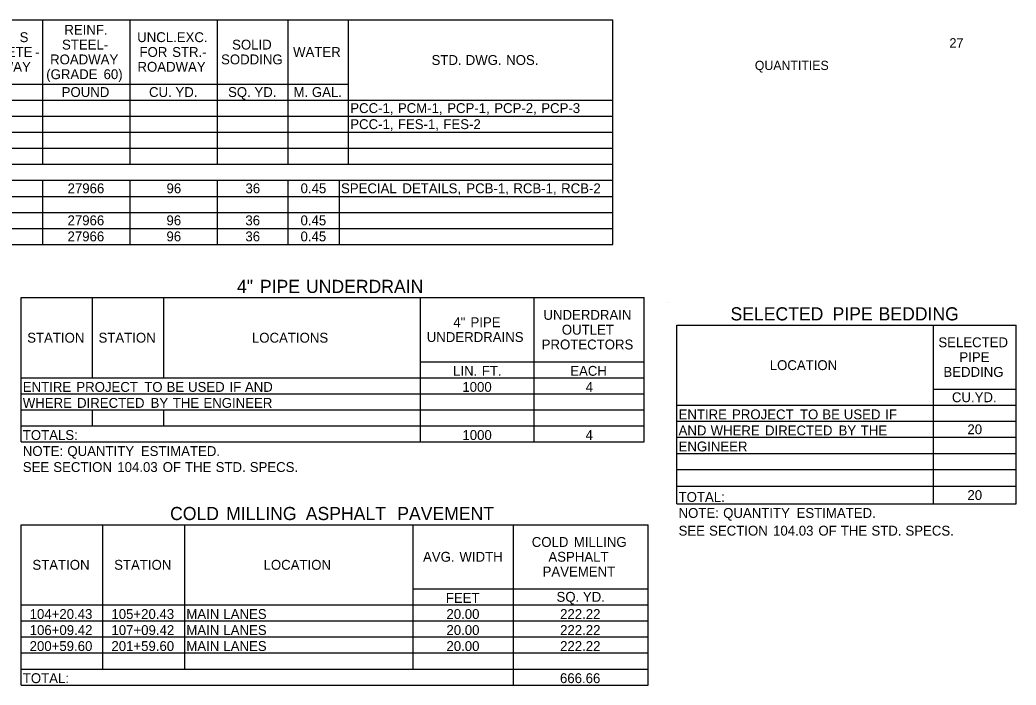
# Model space of a CAD drawing. Extents: x 1334738 to 1334853, y 402732 to 402753.
# Drawn here: x 1334837.83 to 1334852.97, y 402742.15 to 402752.26 of the extents above; entities that cross this region are included whole.
import ezdxf

# ---------------------------------------------------------------- set-up
doc = ezdxf.new("R2010")
doc.units = 0
doc.layers.add('Default', color=7, linetype='Continuous')
doc.layers.add('R_No Plot', color=7, linetype='Continuous')

msp = doc.modelspace()

# ---------------------------------------------------------------- linework, layer by layer
at = {"layer": 'Default'}
for p, q in [((1334821.842, 402752.258), (1334846.839, 402752.258)), ((1334838.174, 402751.04), (1334838.174, 402752.258)), ((1334839.502, 402751.04), (1334839.502, 402752.258)), ((1334840.831, 402751.04), (1334840.831, 402752.258)), ((1334841.903, 402751.283), (1334841.903, 402752.258)), ((1334841.903, 402751.04), (1334841.903, 402752.258)), ((1334842.823, 402750.065), (1334842.823, 402752.258)), ((1334846.839, 402748.846), (1334846.839, 402752.258)), ((1334832.787, 402751.283), (1334842.823, 402751.283)), ((1334821.842, 402751.04), (1334846.839, 402751.04)), ((1334838.174, 402750.065), (1334838.174, 402751.04)), ((1334838.174, 402750.065), (1334838.174, 402751.04)), ((1334839.502, 402750.065), (1334839.502, 402751.04)), ((1334839.502, 402750.065), (1334839.502, 402751.04)), ((1334840.831, 402750.065), (1334840.831, 402751.04)), ((1334840.831, 402750.065), (1334840.831, 402751.04)), ((1334841.903, 402750.065), (1334841.903, 402751.04)), ((1334841.903, 402750.065), (1334841.903, 402751.04)), ((1334842.683, 402751.04), (1334846.839, 402751.04)), ((1334821.842, 402750.796), (1334846.839, 402750.796)), ((1334846.839, 402748.846), (1334846.839, 402750.796)), ((1334821.842, 402750.552), (1334846.839, 402750.552)), ((1334842.683, 402750.552), (1334846.839, 402750.552)), ((1334821.842, 402750.308), (1334846.839, 402750.308)), ((1334841.903, 402750.308), (1334846.839, 402750.308)), ((1334821.842, 402750.065), (1334846.839, 402750.065)), ((1334821.842, 402749.821), (1334846.839, 402749.821)), ((1334838.174, 402748.846), (1334838.174, 402749.821)), ((1334838.174, 402748.846), (1334838.174, 402749.821)), ((1334839.502, 402748.846), (1334839.502, 402749.821)), ((1334839.502, 402748.846), (1334839.502, 402749.821)), ((1334840.831, 402748.846), (1334840.831, 402749.821)), ((1334840.831, 402748.846), (1334840.831, 402749.821)), ((1334841.903, 402748.846), (1334841.903, 402749.821)), ((1334841.903, 402748.846), (1334841.903, 402749.821)), ((1334842.683, 402749.333), (1334842.683, 402749.821)), ((1334842.683, 402748.846), (1334842.683, 402749.821)), ((1334821.842, 402749.577), (1334846.839, 402749.577)), ((1334821.842, 402749.333), (1334846.839, 402749.333)), ((1334825.864, 402749.333), (1334841.903, 402749.333)), ((1334841.903, 402749.333), (1334842.683, 402749.333)), ((1334842.683, 402749.333), (1334846.839, 402749.333)), ((1334821.842, 402749.09), (1334846.839, 402749.09)), ((1334842.683, 402748.846), (1334842.683, 402749.09)), ((1334821.842, 402748.846), (1334846.839, 402748.846)), ((1334837.846, 402748.038), (1334847.315, 402748.038)), ((1334837.846, 402745.844), (1334837.846, 402748.038)), ((1334837.846, 402745.844), (1334837.846, 402748.038)), ((1334838.93, 402746.819), (1334838.93, 402748.038)), ((1334840.015, 402746.819), (1334840.015, 402748.038)), ((1334843.915, 402745.844), (1334843.915, 402748.038)), ((1334845.646, 402745.844), (1334845.646, 402748.038)), ((1334847.315, 402745.844), (1334847.315, 402748.038)), ((1334847.315, 402745.844), (1334847.315, 402748.038)), ((1334847.668, 402747.961), (1334847.668, 402747.961)), ((1334847.814, 402747.62), (1334852.969, 402747.62)), ((1334847.814, 402744.902), (1334847.814, 402747.62)), ((1334847.814, 402744.902), (1334847.814, 402747.62)), ((1334851.714, 402744.902), (1334851.714, 402747.62)), ((1334852.969, 402744.902), (1334852.969, 402747.62)), ((1334852.969, 402744.902), (1334852.969, 402747.62)), ((1334843.915, 402747.063), (1334847.315, 402747.063)), ((1334837.846, 402746.819), (1334847.315, 402746.819)), ((1334837.846, 402746.819), (1334847.315, 402746.819)), ((1334837.846, 402746.575), (1334847.315, 402746.575)), ((1334851.714, 402746.645), (1334852.969, 402746.645)), ((1334847.814, 402746.401), (1334852.969, 402746.401)), ((1334851.714, 402744.902), (1334851.714, 402746.401)), ((1334837.846, 402746.332), (1334847.315, 402746.332)), ((1334838.93, 402746.088), (1334838.93, 402746.332)), ((1334838.93, 402746.088), (1334838.93, 402746.332)), ((1334840.015, 402746.088), (1334840.015, 402746.332)), ((1334840.015, 402746.088), (1334840.015, 402746.332)), ((1334843.915, 402745.844), (1334843.915, 402746.332)), ((1334837.846, 402746.088), (1334847.315, 402746.088)), ((1334847.814, 402746.158), (1334852.969, 402746.158)), ((1334837.846, 402745.844), (1334847.315, 402745.844)), ((1334847.814, 402745.914), (1334852.969, 402745.914)), ((1334847.814, 402745.67), (1334852.969, 402745.67)), ((1334847.814, 402745.426), (1334852.969, 402745.426)), ((1334847.814, 402745.17), (1334852.969, 402745.17)), ((1334847.814, 402744.902), (1334852.969, 402744.902)), ((1334837.846, 402744.586), (1334847.376, 402744.586)), ((1334837.846, 402742.148), (1334837.846, 402744.586)), ((1334837.846, 402742.148), (1334837.846, 402744.586)), ((1334839.089, 402742.392), (1334839.089, 402744.586)), ((1334840.332, 402742.392), (1334840.332, 402744.586)), ((1334843.805, 402742.392), (1334843.805, 402744.586)), ((1334845.329, 402742.148), (1334845.329, 402744.586)), ((1334847.376, 402742.148), (1334847.376, 402744.586)), ((1334847.376, 402742.148), (1334847.376, 402744.586)), ((1334843.805, 402743.611), (1334847.376, 402743.611)), ((1334843.805, 402742.392), (1334843.805, 402743.611)), ((1334837.846, 402743.367), (1334847.376, 402743.367)), ((1334839.089, 402742.392), (1334839.089, 402743.367)), ((1334840.332, 402742.392), (1334840.332, 402743.367)), ((1334845.329, 402742.392), (1334845.329, 402743.367)), ((1334837.846, 402743.123), (1334847.376, 402743.123)), ((1334837.846, 402742.879), (1334847.376, 402742.879)), ((1334837.846, 402742.636), (1334847.376, 402742.636)), ((1334837.846, 402742.392), (1334839.089, 402742.392)), ((1334837.846, 402742.392), (1334847.376, 402742.392)), ((1334839.089, 402742.392), (1334840.332, 402742.392)), ((1334840.332, 402742.392), (1334843.805, 402742.392)), ((1334845.329, 402742.392), (1334847.376, 402742.392)), ((1334837.846, 402742.148), (1334847.376, 402742.148))]:
    msp.add_line(p, q, dxfattribs=at)

# ---------------------------------------------------------------- texts
for s, height, p in [('REINF.', 0.15, (1334838.502, 402752.033)), (' S', 0.15, (1334837.766, 402751.921)), ('UNCL.EXC.', 0.15, (1334839.609, 402751.921)), ('CONCRETE', 0.15, (1334836.892, 402751.696)), ('STEEL-', 0.15, (1334838.466, 402751.808)), ('FOR', 0.15, (1334839.644, 402751.696)), (' STR.-', 0.15, (1334840.085, 402751.696)), ('SOLID', 0.15, (1334841.052, 402751.808)), ('WATER', 0.15, (1334841.979, 402751.696)), ('-', 0.15, (1334838.058, 402751.696)), ('ROADWAY', 0.15, (1334838.285, 402751.583)), ('SODDING', 0.15, (1334840.884, 402751.583)), ('STD.', 0.15, (1334844.084, 402751.574)), (' DWG.', 0.15, (1334844.547, 402751.574)), (' NOS.', 0.15, (1334845.162, 402751.574)), ('ROADWAY', 0.15, (1334836.956, 402751.471)), ('ROADWAY', 0.15, (1334839.613, 402751.471)), ('(GRADE', 0.15, (1334838.226, 402751.358)), (' 60)', 0.15, (1334839.042, 402751.358)), ('POUND', 0.15, (1334838.461, 402751.087)), ('CU. YD.', 0.15, (1334839.789, 402751.087)), ('SQ. YD.', 0.15, (1334840.99, 402751.087)), ('M. GAL.', 0.15, (1334841.986, 402751.087)), ('PCC-1,', 0.15, (1334842.848, 402750.843)), (' PCM-1,', 0.15, (1334843.516, 402750.843)), (' PCP-1,', 0.15, (1334844.266, 402750.843)), (' PCP-2,', 0.15, (1334844.981, 402750.843)), (' PCP-3', 0.15, (1334845.696, 402750.843)), ('PCC-1,', 0.15, (1334842.848, 402750.599)), (' FES-1,', 0.15, (1334843.516, 402750.599)), (' FES-2', 0.15, (1334844.208, 402750.599)), ('27966', 0.15, (1334838.551, 402749.624)), ('96', 0.15, (1334840.055, 402749.624)), ('36', 0.15, (1334841.255, 402749.624)), ('0.45', 0.15, (1334842.093, 402749.624)), ('SPECIAL', 0.15, (1334842.707, 402749.624)), (' DETAILS,', 0.15, (1334843.585, 402749.624)), (' PCB-1,', 0.15, (1334844.557, 402749.624)), (' RCB-1,', 0.15, (1334845.272, 402749.624)), (' RCB-2', 0.15, (1334845.998, 402749.624)), ('27966', 0.15, (1334838.55, 402749.137)), ('96', 0.15, (1334840.054, 402749.137)), ('36', 0.15, (1334841.254, 402749.137)), ('0.45', 0.15, (1334842.092, 402749.137)), ('27966', 0.15, (1334838.55, 402748.893)), ('96', 0.15, (1334840.054, 402748.893)), ('36', 0.15, (1334841.254, 402748.893)), ('0.45', 0.15, (1334842.092, 402748.893)), ('4"', 0.2, (1334841.126, 402748.108)), (' PIPE', 0.2, (1334841.4, 402748.108)), (' UNDERDRAIN', 0.2, (1334842.101, 402748.108)), ('SELECTED', 0.2, (1334848.628, 402747.691)), (' PIPE', 0.2, (1334850.105, 402747.691)), (' BEDDING', 0.2, (1334850.806, 402747.691)), ('4"', 0.15, (1334844.415, 402747.588)), (' PIPE', 0.15, (1334844.62, 402747.588)), ('UNDERDRAIN', 0.15, (1334845.785, 402747.7)), ('OUTLET', 0.15, (1334846.064, 402747.475)), ('STATION', 0.15, (1334837.937, 402747.353)), ('STATION', 0.15, (1334839.021, 402747.353)), ('LOCATIONS', 0.15, (1334841.353, 402747.353)), ('UNDERDRAINS', 0.15, (1334844.011, 402747.363)), ('SELECTED', 0.15, (1334851.788, 402747.283)), ('PROTECTORS', 0.15, (1334845.758, 402747.25)), ('PIPE', 0.15, (1334852.108, 402747.058)), ('LIN.', 0.15, (1334844.411, 402746.849)), (' FT.', 0.15, (1334844.792, 402746.849)), ('EACH', 0.15, (1334846.192, 402746.849)), ('LOCATION', 0.15, (1334849.225, 402746.936)), ('BEDDING', 0.15, (1334851.865, 402746.833)), ('ENTIRE', 0.15, (1334837.87, 402746.605)), (' PROJECT', 0.15, (1334838.628, 402746.605)), (' TO', 0.15, (1334839.66, 402746.605)), (' BE', 0.15, (1334840, 402746.605)), (' USED', 0.15, (1334840.326, 402746.605)), (' IF', 0.15, (1334840.956, 402746.605)), (' AND', 0.15, (1334841.191, 402746.605)), ('1000', 0.15, (1334844.552, 402746.605)), ('4', 0.15, (1334846.427, 402746.605)), ('CU.YD.', 0.15, (1334851.994, 402746.448)), ('WHERE', 0.15, (1334837.87, 402746.362)), (' DIRECTED', 0.15, (1334838.639, 402746.362)), (' BY', 0.15, (1334839.757, 402746.362)), (' THE', 0.15, (1334840.094, 402746.362)), (' ENGINEER', 0.15, (1334840.56, 402746.362)), ('ENTIRE', 0.15, (1334847.839, 402746.188)), (' PROJECT', 0.15, (1334848.596, 402746.188)), (' TO', 0.15, (1334849.628, 402746.188)), (' BE', 0.15, (1334849.968, 402746.188)), (' USED', 0.15, (1334850.295, 402746.188)), (' IF', 0.15, (1334850.924, 402746.188)), ('AND', 0.15, (1334847.839, 402745.944)), (' WHERE', 0.15, (1334848.27, 402745.944)), (' DIRECTED', 0.15, (1334849.097, 402745.944)), (' BY', 0.15, (1334850.215, 402745.944)), (' THE', 0.15, (1334850.552, 402745.944)), ('20', 0.15, (1334852.23, 402745.961)), ('TOTALS:', 0.15, (1334837.87, 402745.874)), ('1000', 0.15, (1334844.553, 402745.874)), ('4', 0.15, (1334846.425, 402745.874)), ('NOTE:', 0.15, (1334837.87, 402745.63)), (' QUANTITY', 0.15, (1334838.492, 402745.63)), (' ESTIMATED.', 0.15, (1334839.609, 402745.63)), ('ENGINEER', 0.15, (1334847.839, 402745.7)), ('SEE', 0.15, (1334837.87, 402745.387)), (' SECTION', 0.15, (1334838.278, 402745.387)), (' 104.03', 0.15, (1334839.251, 402745.387)), (' OF', 0.15, (1334839.941, 402745.387)), (' THE', 0.15, (1334840.28, 402745.387)), (' STD.', 0.15, (1334840.746, 402745.387)), (' SPECS.', 0.15, (1334841.264, 402745.387)), ('TOTAL:', 0.15, (1334847.839, 402744.932)), ('20', 0.15, (1334852.23, 402744.961)), ('COLD', 0.2, (1334840.109, 402744.656)), (' MILLING', 0.2, (1334840.887, 402744.656)), (' ASPHALT', 0.2, (1334842.097, 402744.656)), (' PAVEMENT', 0.2, (1334843.488, 402744.656)), ('NOTE:', 0.15, (1334847.839, 402744.689)), (' QUANTITY', 0.15, (1334848.461, 402744.689)), (' ESTIMATED.', 0.15, (1334849.577, 402744.689)), ('SEE', 0.15, (1334847.839, 402744.42)), (' SECTION', 0.15, (1334848.247, 402744.42)), (' 104.03', 0.15, (1334849.22, 402744.42)), (' OF', 0.15, (1334849.909, 402744.42)), (' THE', 0.15, (1334850.249, 402744.42)), (' STD.', 0.15, (1334850.715, 402744.42)), (' SPECS.', 0.15, (1334851.232, 402744.42)), ('COLD', 0.15, (1334845.607, 402744.248)), (' MILLING', 0.15, (1334846.191, 402744.248)), ('AVG.', 0.15, (1334843.954, 402744.023)), (' WIDTH', 0.15, (1334844.452, 402744.023)), ('ASPHALT', 0.15, (1334845.86, 402744.023)), ('STATION', 0.15, (1334838.016, 402743.901)), ('STATION', 0.15, (1334839.259, 402743.901)), ('LOCATION', 0.15, (1334841.53, 402743.901)), ('PAVEMENT', 0.15, (1334845.772, 402743.798)), ('FEET', 0.15, (1334844.301, 402743.397)), ('SQ.', 0.15, (1334845.983, 402743.414)), (' YD.', 0.15, (1334846.329, 402743.414)), ('104+20.43', 0.15, (1334837.974, 402743.153)), ('105+20.43', 0.15, (1334839.217, 402743.153)), ('MAIN', 0.15, (1334840.356, 402743.153)), (' LANES', 0.15, (1334840.863, 402743.153)), ('20.00', 0.15, (1334844.31, 402743.153)), ('222.22', 0.15, (1334846.038, 402743.153)), ('106+09.42', 0.15, (1334837.975, 402742.909)), ('107+09.42', 0.15, (1334839.218, 402742.909)), ('MAIN', 0.15, (1334840.356, 402742.909)), (' LANES', 0.15, (1334840.863, 402742.909)), ('20.00', 0.15, (1334844.31, 402742.909)), ('222.22', 0.15, (1334846.038, 402742.909)), ('200+59.60', 0.15, (1334837.974, 402742.666)), ('201+59.60', 0.15, (1334839.217, 402742.666)), ('MAIN', 0.15, (1334840.356, 402742.666)), (' LANES', 0.15, (1334840.863, 402742.666)), ('20.00', 0.15, (1334844.31, 402742.666)), ('222.22', 0.15, (1334846.038, 402742.666)), ('TOTAL:', 0.15, (1334837.87, 402742.178)), ('666.66', 0.15, (1334846.036, 402742.178))]:
    msp.add_text(s, height=height, dxfattribs=at).set_placement(p)
at = {"layer": 'R_No Plot'}
msp.add_text('27', height=0.1444, dxfattribs=at).set_placement((1334851.956, 402751.836))
msp.add_text('QUANTITIES', height=0.14, rotation=360, dxfattribs=at).set_placement((1334848.998, 402751.497))

doc.saveas('drawing.dxf')
